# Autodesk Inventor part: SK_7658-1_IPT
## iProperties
Created: 2008-01
Part Number: SK_7658-1_IPT
Document SubType Name: Modellieren
Designer: Borrello
Density: 1 g/cm^3
Description: Halter
Mass: 1.28253 g
Surface Area: 19.5146 cm^2
Volume: 1.28253 cm^3
AIMD_PARTNO: SK 7658-1
CIN_WERKSTOFF_01: siehe
CIN_WERKSTOFF_02: Zeichnung
CIN_AUS_ROHTEIL: -
Author: Borrello
Title: Halter
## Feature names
1. Extrusion1
2. Extrusion10
3. Extrusion16
4. Fase14 [Chamfer]
5. Rundung39 [Fillet]
6. Sweeping10
7. Extrusion17
8. Sweeping11
9. Sweeping12
10. Erhebung9
11. Rundung45 [Fillet]
12. Rundung46 [Fillet]
13. Rundung47 [Fillet]
14. Rundung48 [Fillet]
15. Extrusion18
16. Rundung55 [Fillet]
17. Rundung56 [Fillet]
18. Rundung57 [Fillet]
19. Grobblech1
